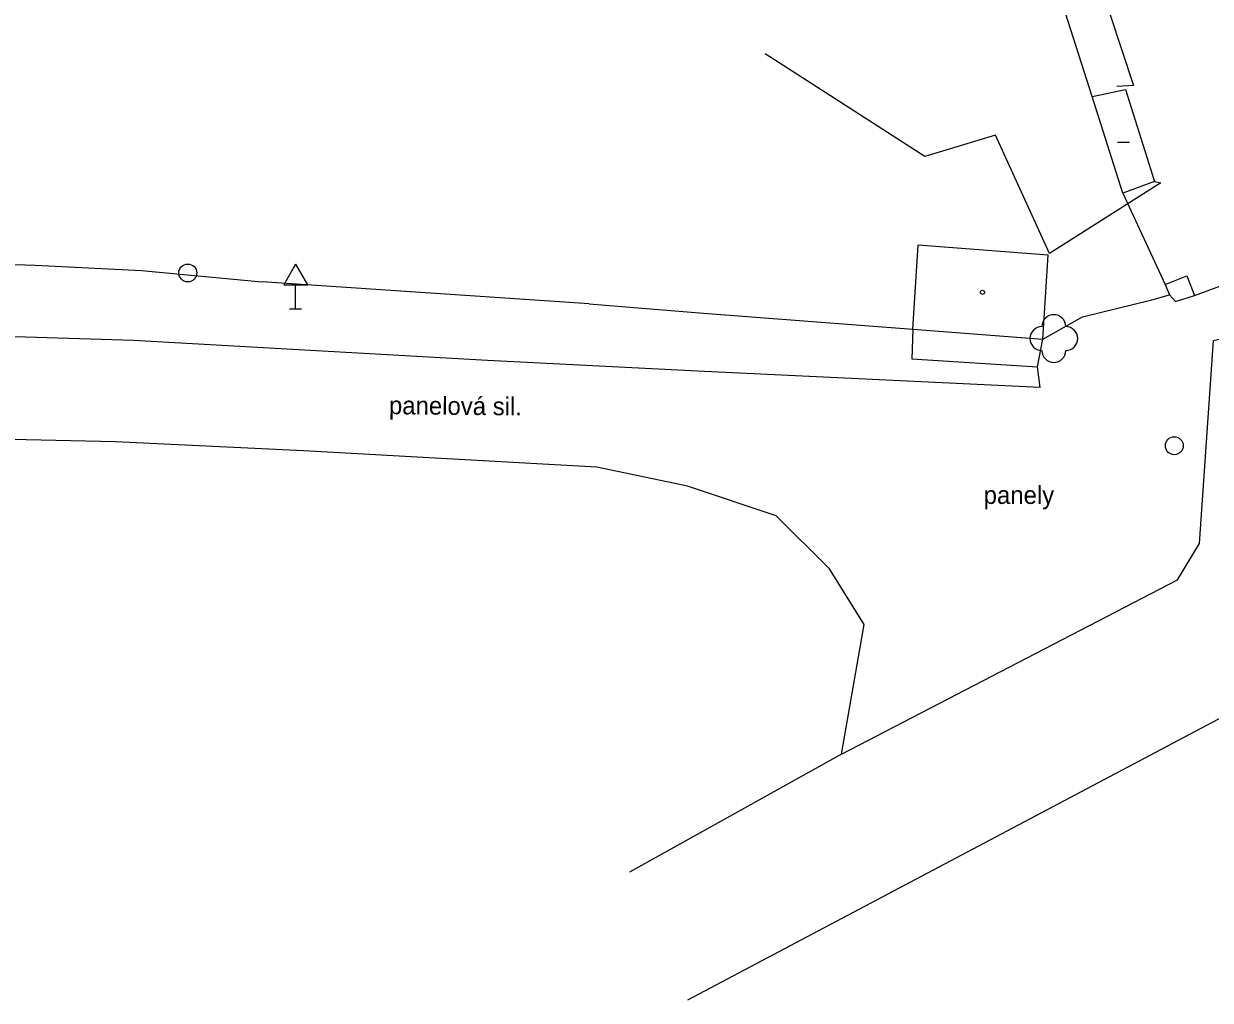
# Model space of a CAD drawing. Extents: x -762483 to -761175, y -1154655 to -1152452.
# Drawn here: x -762351.03 to -762301.29, y -1152963.14 to -1152922.22 of the extents above; entities that cross this region are included whole.
import ezdxf

# ---------------------------------------------------------------- set-up
doc = ezdxf.new("R2010")
doc.units = 0
for name, color, linetype in [('BUDOVY_MĚŘ', 7, 'Continuous'), ('MAP_ZN_BP', 7, 'Continuous'), ('POMOC_POPIS', 7, 'Continuous'), ('ROZHRANÍ_PLOCH', 7, 'Continuous'), ('ZELEŇ', 7, 'Continuous'), ('ZN_BUDOV', 7, 'Continuous'), ('ZN_DOPLŇKOVÉ', 7, 'Continuous')]:
    doc.layers.add(name, color=color, linetype=linetype)

msp = doc.modelspace()

# ---------------------------------------------------------------- linework, layer by layer
at = {"layer": 'BUDOVY_MĚŘ'}
for p, q in [((-762313.76, -1152935.02), (-762313.54, -1152931.5)), ((-762308.09, -1152931.92), (-762313.54, -1152931.5)), ((-762308.31, -1152935.44), (-762308.09, -1152931.92)), ((-762313.76, -1152935.02), (-762308.31, -1152935.44))]:
    msp.add_line(p, q, dxfattribs=at)
msp.add_lwpolyline([(-762306.24, -1152925.27), (-762304.85, -1152924.97), (-762303.63, -1152928.83), (-762304.96, -1152929.32), (-762306.24, -1152925.27)], dxfattribs=at)
at = {"layer": 'MAP_ZN_BP'}
for centre, radius in [((-762344.15, -1152932.66), 0.375), ((-762344.15, -1152932.66), 0.0005), ((-762302.8, -1152939.9), 0.375), ((-762302.8, -1152939.9), 0.0005)]:
    msp.add_circle(centre, radius, dxfattribs=at)
at = {"layer": 'ROZHRANÍ_PLOCH'}
for p, q in [((-762313.76, -1152935.02), (-762313.8, -1152936.26)), ((-762331.59, -1152936.33), (-762346.43, -1152935.49)), ((-762308.53, -1152936.59), (-762308.31, -1152935.44)), ((-762322.79, -1152936.77), (-762331.59, -1152936.33)), ((-762313.8, -1152936.26), (-762308.53, -1152936.59)), ((-762308.42, -1152937.46), (-762322.79, -1152936.77)), ((-762308.42, -1152937.46), (-762308.53, -1152936.59)), ((-762339.3, -1152940.12), (-762347.18, -1152939.73)), ((-762327, -1152940.8), (-762339.3, -1152940.12)), ((-762323.21, -1152941.6), (-762327, -1152940.8)), ((-762319.49, -1152942.84), (-762323.21, -1152941.6)), ((-762317.25, -1152945.06), (-762319.49, -1152942.84)), ((-762315.8, -1152947.39), (-762317.25, -1152945.06))]:
    msp.add_line(p, q, dxfattribs=at)
for points in [[(-762303.63, -1152928.83), (-762303.36, -1152928.88), (-762308.03, -1152931.85), (-762310.29, -1152926.89), (-762313.25, -1152927.78), (-762319.95, -1152923.48)], [(-762268.07, -1152933.91), (-762279.87, -1152940.33), (-762294.74, -1152948.08), (-762323.2, -1152963.14)], [(-762316.75, -1152952.82), (-762302.67, -1152945.52), (-762301.74, -1152944), (-762301.16, -1152935.49), (-762296.04, -1152934.31)], [(-762346.43, -1152935.49), (-762356.39, -1152935.18), (-762376.9, -1152934.77), (-762386.61, -1152934.84), (-762398.4, -1152934.59), (-762408.77, -1152934.59)], [(-762347.18, -1152939.73), (-762368.41, -1152939.26), (-762372.29, -1152941.27), (-762374.03, -1152942.58), (-762375.2, -1152944.13), (-762376.52, -1152946.79), (-762375.35, -1152946.91), (-762375.34, -1152948.42)], [(-762316.75, -1152952.82), (-762315.8, -1152947.39)], [(-762316.75, -1152952.82), (-762325.64, -1152957.77)]]:
    msp.add_lwpolyline(points, dxfattribs=at)
at = {"layer": 'ZELEŇ'}
msp.add_circle((-762307.85, -1152935.41), 0.0005, dxfattribs=at)
for centre, start, end in [((-762307.85, -1152934.91), 0, 180), ((-762308.35, -1152935.41), 90, 270), ((-762307.35, -1152935.41), 270, 90), ((-762307.85, -1152935.91), 180, 360)]:
    msp.add_arc(centre, 0.5, start, end, dxfattribs=at)
at = {"layer": 'ZN_BUDOV'}
msp.add_line((-762305.18, -1152927.18), (-762304.68, -1152927.18), dxfattribs=at)
msp.add_circle((-762310.84, -1152933.47), 0.0875, dxfattribs=at)
at = {"layer": 'ZN_DOPLŇKOVÉ'}
for p, q in [((-762339.63, -1152932.294), (-762340.13, -1152933.16)), ((-762339.63, -1152932.294), (-762339.13, -1152933.16)), ((-762346.09, -1152932.56), (-762341.05, -1152933.03)), ((-762327.32, -1152933.95), (-762341.05, -1152933.03)), ((-762340.13, -1152933.16), (-762339.13, -1152933.16)), ((-762339.63, -1152934.16), (-762339.63, -1152933.16)), ((-762339.88, -1152934.16), (-762339.38, -1152934.16)), ((-762327.32, -1152933.95), (-762322.53, -1152934.34)), ((-762322.53, -1152934.34), (-762313.76, -1152935.02))]:
    msp.add_line(p, q, dxfattribs=at)
for points in [[(-762306.24, -1152925.27), (-762313.96, -1152901.15), (-762338.79, -1152917.93), (-762339.38, -1152917.25), (-762341.38, -1152914.91)], [(-762307.69, -1152918.94), (-762306.5, -1152918.78), (-762304.51, -1152924.81), (-762305.21, -1152924.85)], [(-762304.96, -1152929.32), (-762303.19, -1152933.15)], [(-762301.96, -1152933.6), (-762297.02, -1152931.79)], [(-762352.69, -1152932.26), (-762350.55, -1152932.34)], [(-762350.55, -1152932.34), (-762346.09, -1152932.56)], [(-762303.19, -1152933.15), (-762302.27, -1152932.78)], [(-762302.27, -1152932.78), (-762301.96, -1152933.6)], [(-762303.19, -1152933.15), (-762303, -1152933.57)], [(-762306.65, -1152934.5), (-762303.74, -1152933.79)], [(-762303.74, -1152933.79), (-762303, -1152933.57)], [(-762303, -1152933.57), (-762302.75, -1152933.86), (-762301.96, -1152933.6)], [(-762308.31, -1152935.44), (-762306.65, -1152934.5)]]:
    msp.add_lwpolyline(points, dxfattribs=at)

# ---------------------------------------------------------------- texts
at = {"layer": 'POMOC_POPIS'}
msp.add_text('panelová sil.', height=0.75, rotation=359.4967, dxfattribs=at).set_placement((-762335.72, -1152938.58))
msp.add_text('panely', height=0.75, dxfattribs=at).set_placement((-762310.79, -1152942.34))

doc.saveas('drawing.dxf')
